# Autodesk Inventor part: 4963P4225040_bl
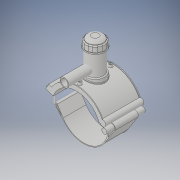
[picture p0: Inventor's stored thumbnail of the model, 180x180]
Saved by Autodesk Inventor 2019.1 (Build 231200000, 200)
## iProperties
Created: 2017-07
Part Number: 4963P4225040_bl
Material: Generic
Document SubType Name: Modeling
Designer: KIM
Density: 1 g/cm^3
Appearance: Default
Author: KIM
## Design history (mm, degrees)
derived "4963P4.ipt"
feature "Solid1::4963P4.ipt" dims "ScaleForDerivedMember" = 10
feature "Solid2::4963P4.ipt" dims "ScaleForDerivedMember" = 10
feature "Solid3::4963P4.ipt" dims "ScaleForDerivedMember" = 10
tag "TaggingFeature1"
body "Solid1"
body "Solid2"
body "Solid3"
other parameters: "d_" = 225 [user parameter], "B_" = 227 [user parameter], "L_" = 176 [user parameter], "d_t" = 6 [user parameter], "H_2" = 177 [user parameter], "H_" = 142 [user parameter], "d1" = 261 [user parameter], "d148" = 3.375 [user parameter], "d160" = 3.375 [user parameter], "d169" = 3.375 [user parameter], "d192" = 7.2 [user parameter], "d0" = 225 [user parameter], "d2" = 295.1 [user parameter], "d3" = 56.25 [user parameter], "d4" = 176 [user parameter], "d5" = 0 [user parameter], "d6" = 0.1 [user parameter], "d8" = 0 [user parameter], "d19" = 6 [user parameter], "d20" = 6 [user parameter], "d21" = 105.6 [user parameter], "d23" = 0 [user parameter], "d24" = 52.8 [user parameter], "d26" = 0 [user parameter], "d27" = 3 [user parameter], "d28" = 3 [user parameter], "d29" = 3 [user parameter], "d30" = 75 [user parameter], "d31" = 6 [user parameter], "d32" = 0 [user parameter], "d33" = 0 [user parameter], "d34" = 0.6 [user parameter], "d40" = 135.72 [user parameter], "d43" = 0 [user parameter], "d45" = 0 [user parameter], "d47" = 236.1 [user parameter], "d70" = 15 [user parameter], "d72" = 0 [user parameter], "d73" = 6 [user parameter], "d75" = 5 [user parameter], "d76" = 0 [user parameter], "d77" = 11.25 [user parameter], "d78" = 142.5 [user parameter], "d79" = 15 [user parameter], "d80" = 70.4 [user parameter], "d82" = 5 deg [user parameter], "d84" = 4 [user parameter], "d85" = 14 [user parameter], "d86" = 0 [user parameter], "d87" = 3 [user parameter], "d88" = 0 [user parameter], "d89" = 1 [user parameter], "d90" = 1 [user parameter], "d91" = 140.8 [user parameter], "d92" = 0 [user parameter], "d93" = 0.5 [user parameter], "d94" = 118.42105 [user parameter], "d96" = 266.22 [user parameter], "d97" = 3.52 [user parameter], "d98" = 0 [user parameter], "d102" = 2.25 [user parameter], "d120" = 140 deg [user parameter], "d121" = 24.228 [user parameter], "d122" = 20 deg [user parameter], "d123" = 522 [user parameter], "d124" = 156.6 [user parameter], "d126" = 0 [user parameter], "d143" = 231.75 [user parameter], "d145" = 27.69231 [user parameter], "d149" = 3.375 [user parameter], "d150" = 30.46154 [user parameter], "d153" = 176 [user parameter], "d154" = 0 [user parameter], "d156" = 130.5 [user parameter], "d157" = 160 deg [user parameter], "d159" = 7.2 [user parameter], "d161" = 3.375 [user parameter], "d162" = 105.6 [user parameter], "d163" = 0 [user parameter], "d164" = 112.5 [user parameter], "d167" = 22.5 [user parameter], "d168" = 127.31707 [user parameter], "d170" = 3.375 [user parameter], "d172" = 0 [user parameter], "d173" = 1 [user parameter], "d175" = 112.5 [user parameter], "d176" = 20 deg [user parameter], "d177" = 15.75 [user parameter], "d178" = 36 [user parameter], "d180" = 0 [user parameter], "d183" = 14.4 [user parameter], "d184" = 12.6 [user parameter], "d185" = 57.2 [user parameter], "d186" = 57.2 [user parameter], "d187" = 130.5 [user parameter], "d188" = 10.8 [user parameter], "d189" = 15.75 [user parameter], "d190" = 0 [user parameter], "d191" = 195.75 [user parameter], "d193" = 7.2 [user parameter], "d194" = 6.16 [user parameter], "d195" = 90 deg [user parameter], "d197" = 0 [user parameter], "d199" = 0 [user parameter], "d200" = 18 [user parameter], "d202" = 0 [user parameter], "d203" = 177 [user parameter], "d204" = 85.5 [user parameter], "d205" = 63 [user parameter], "d206" = 76.5 [user parameter], "d207" = 132.75 [user parameter], "d208" = 138.06 [user parameter], "d209" = 164.61 [user parameter], "d210" = 77.4 [user parameter], "d212" = 72 [user parameter], "d213" = 36 [user parameter], "d216" = 0 [user parameter], "d217" = 22.5 [user parameter], "d218" = 22.5 [user parameter], "d219" = 4.5 [user parameter]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
